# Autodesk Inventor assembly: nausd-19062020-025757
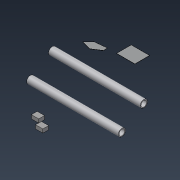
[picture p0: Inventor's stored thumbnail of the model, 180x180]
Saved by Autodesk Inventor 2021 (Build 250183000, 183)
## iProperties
Created: 2020-06
Part Number: nausd-19062020-025757
Material: Všeobecné
Document SubType Name: Assembly
Designer: naus
Mass: 139.627 g
Surface Area: 648.069 cm^2
Volume: 69.1997 cm^3
Density: 2.01774 g/cm^3
a21_Hustota: 7850 kg/m^3
a23_Polozka_slouceni: s
Date Saved: 19062020
Saved By: nausd
Time Saved: 025757
a24_Objem_Media: ne
Author: naus
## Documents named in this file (5)
- C:\iLogic_Main\iLogic_UI\Workspaces\Pracovní prostředí\kusovnik\nausd-19062020-025757.iam
- C:\iLogic_Main\iLogic_UI\Workspaces\Pracovní prostředí\kusovnik\nausd-19062020-025718.ipt
- C:\iLogic_Main\iLogic_UI\Workspaces\Pracovní prostředí\kusovnik\WAVIN TRUBKA PP-R 20x2,2 - 250 S 5 (PN 10) SDR 11.ipt
- C:\iLogic_Main\iLogic_UI\Workspaces\Pracovní prostředí\kusovnik\test_19_12.ipt
- C:\iLogic_Main\iLogic_UI\Workspaces\Pracovní prostředí\kusovnik\TESTEST.ipt
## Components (6 placed, 4 different names)
1. nausd-19062020-025718:1
2. nausd-19062020-025718:2
3. WAVIN TRUBKA PP-R 20x2,2 - 250 S 5 (PN 10) SDR 11:1
4. WAVIN TRUBKA PP-R 20x2,2 - 250 S 5 (PN 10) SDR 11:2
5. test_19_12:1
6. TESTEST:1
